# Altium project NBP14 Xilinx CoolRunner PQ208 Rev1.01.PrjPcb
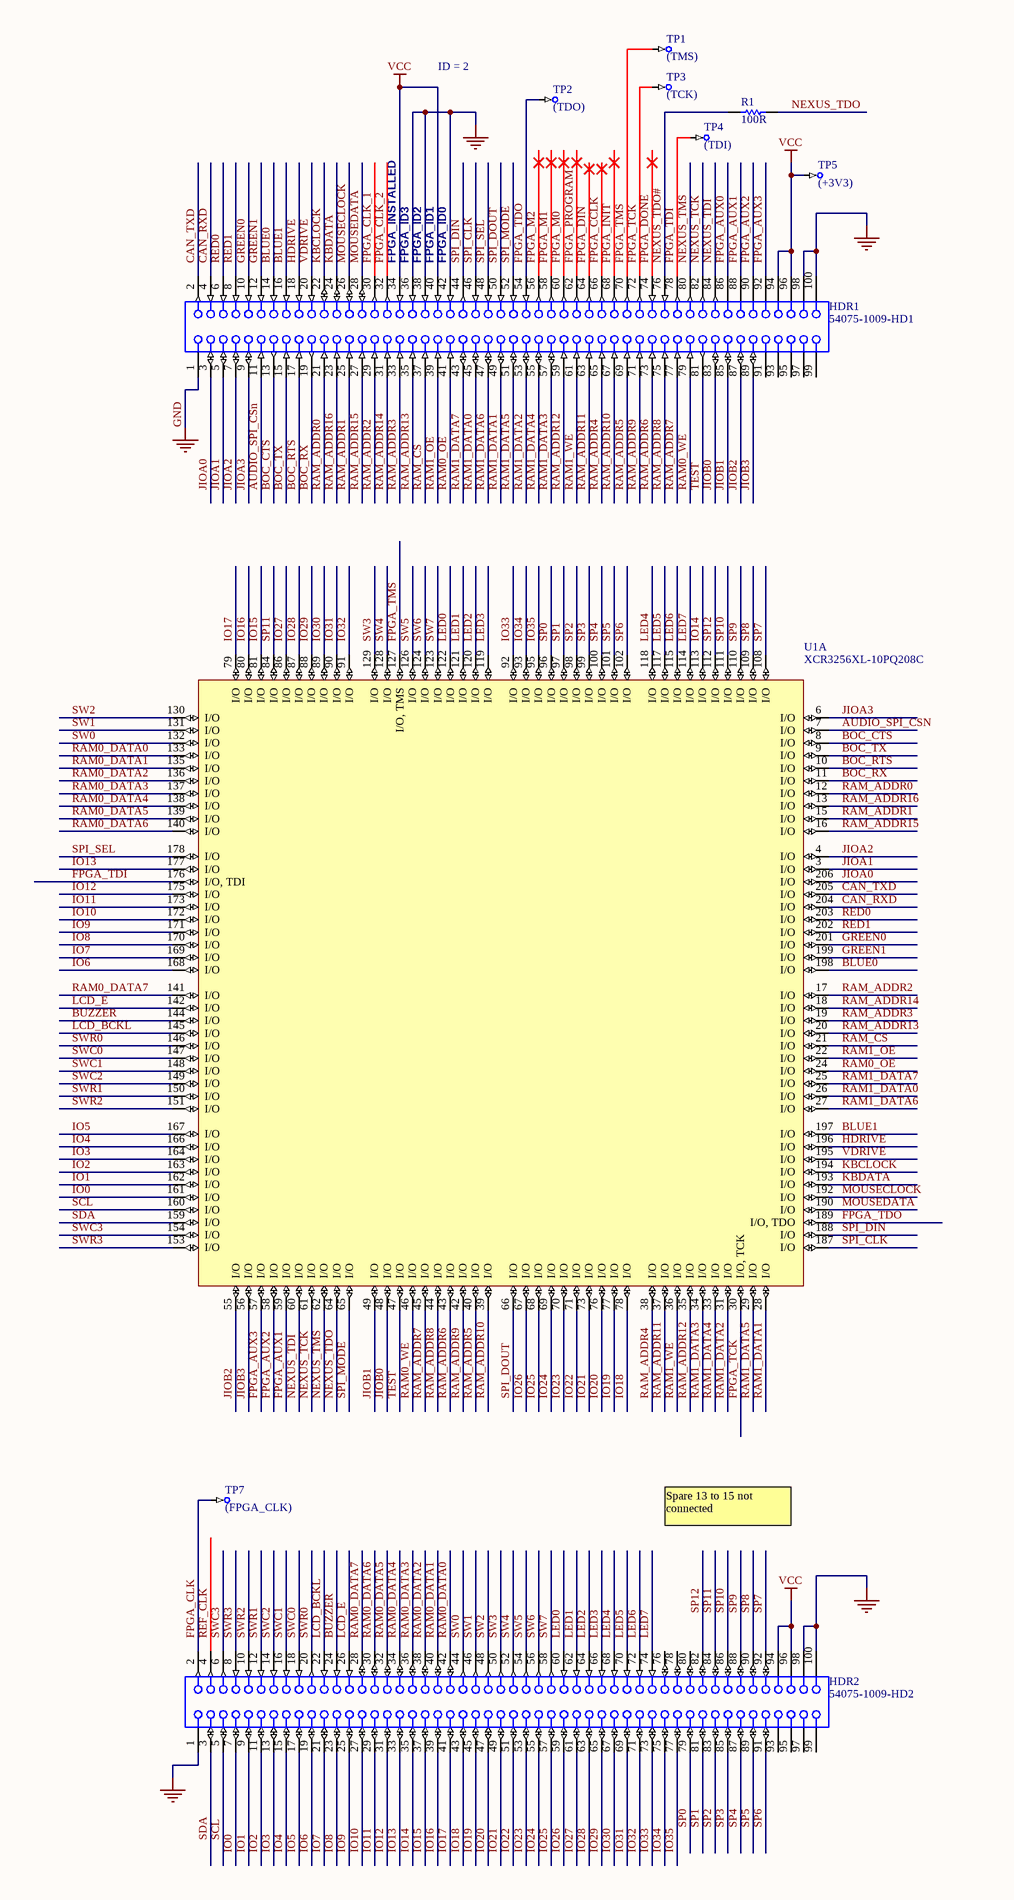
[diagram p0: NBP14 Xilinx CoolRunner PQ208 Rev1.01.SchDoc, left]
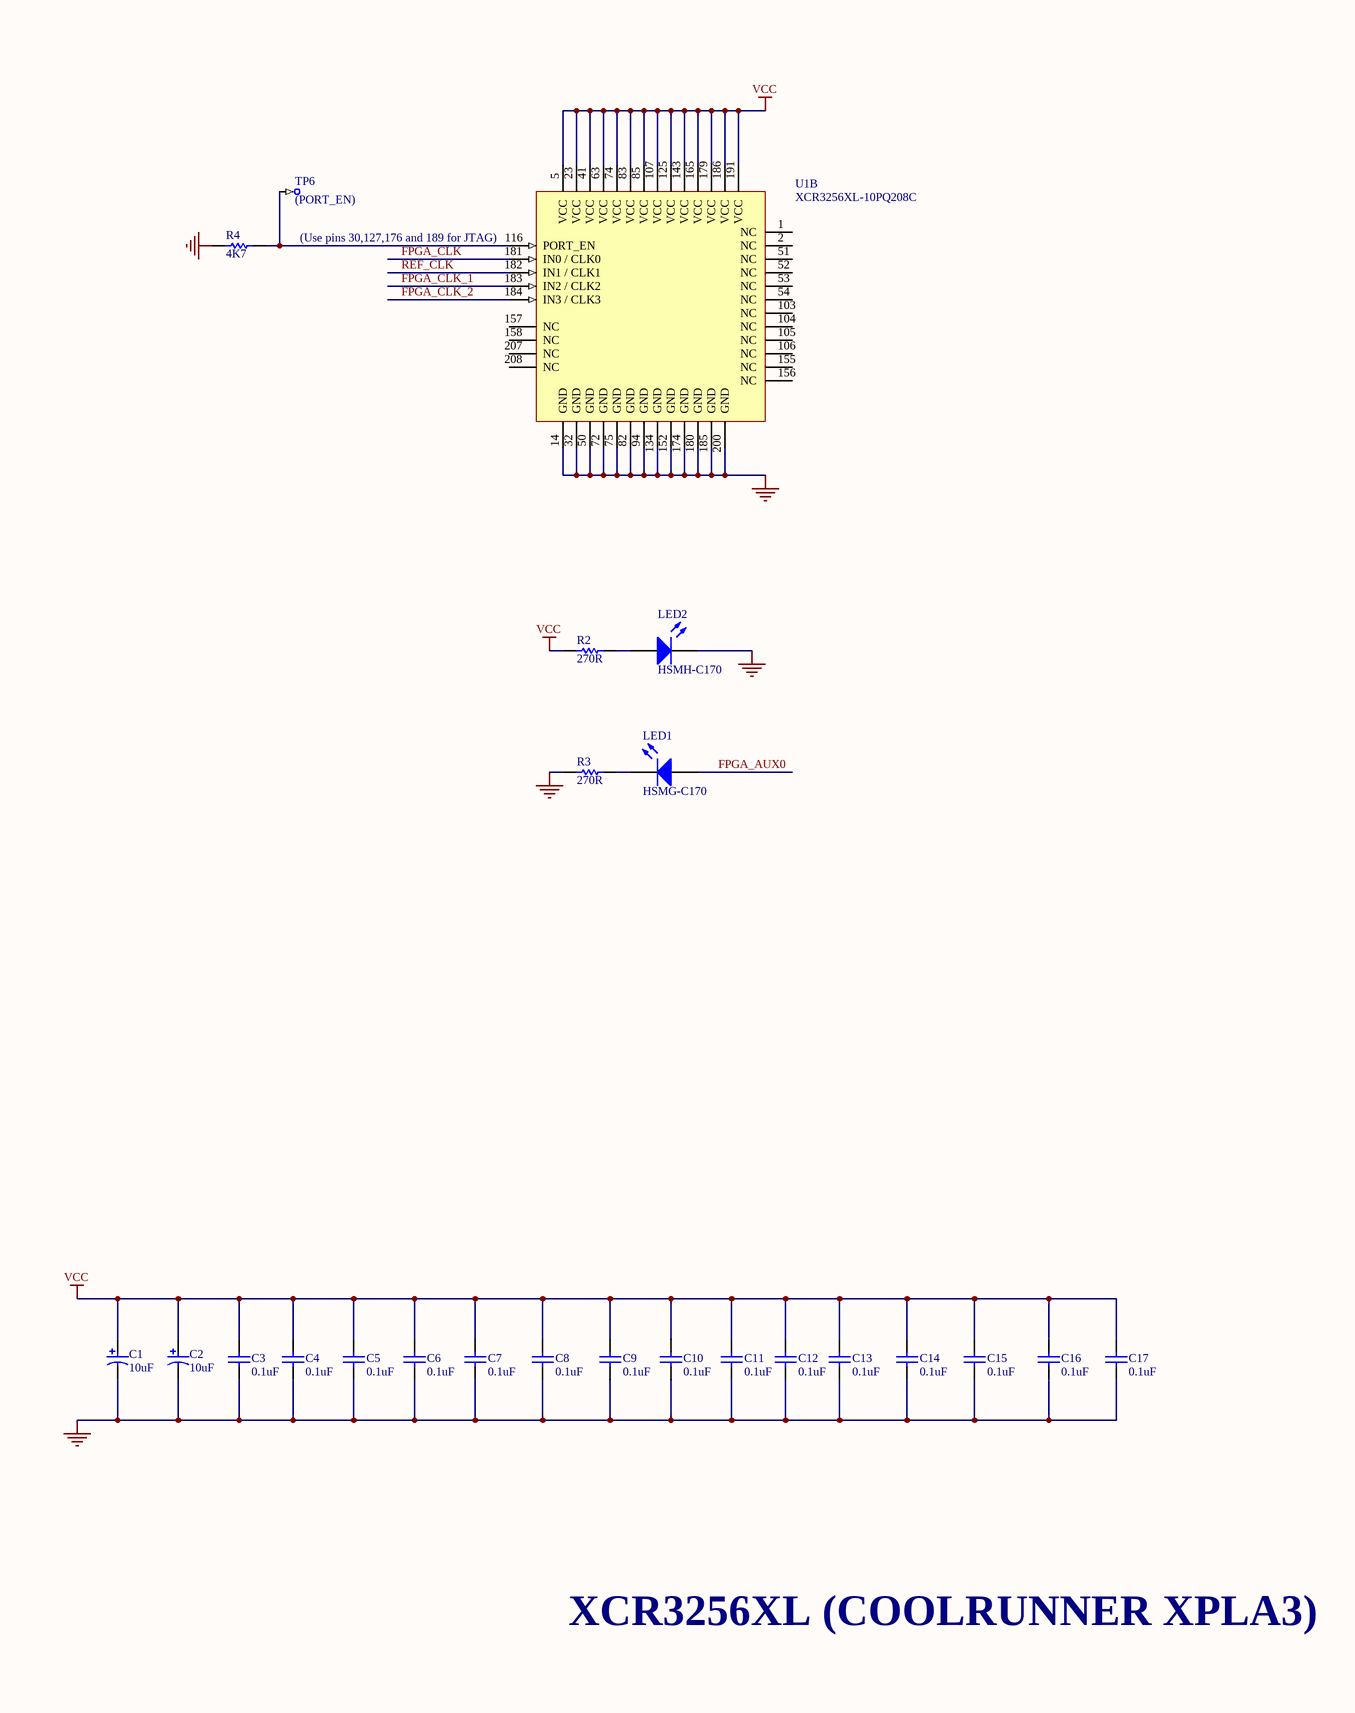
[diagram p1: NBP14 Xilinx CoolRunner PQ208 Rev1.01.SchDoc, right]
1 sheet, 33 parts. Net scope: global (net labels, ports and power ports of the same name join across sheets).
Board file: NBP14 Xilinx CoolRunner PQ208 Rev1.01.PcbDoc

## Sheet NBP14 Xilinx CoolRunner PQ208 Rev1.01.SchDoc: CoolRunner XPLA3 Daughter Board
size A2; Organization: Altium Limited; Address1: L3, 12a Rodborough Rd; Address2: Frenchs Forest; Address3: NSW; Address4: Australia 2086; DocumentNumber: 1; Revision: 1.01; SheetNumber: 1; SheetTotal: 1

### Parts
C1  10uF  [MCCT-B]
C2  10uF  [MCCT-B]
C3  0.1uF  [CC2012-0805]
C4  0.1uF  [CC2012-0805]
C5  0.1uF  [CC2012-0805]
C6  0.1uF  [CC2012-0805]
C7  0.1uF  [CC2012-0805]
C8  0.1uF  [CC2012-0805]
C9  0.1uF  [CC2012-0805]
C10  0.1uF  [CC2012-0805]
C11  0.1uF  [CC2012-0805]
C12  0.1uF  [CC2012-0805]
C13  0.1uF  [CC2012-0805]
C14  0.1uF  [CC2012-0805]
C15  0.1uF  [CC2012-0805]
C16  0.1uF  [CC2012-0805]
C17  0.1uF  [CC2012-0805]
HDR1  54075-1009-HD1  [54075]
HDR2  54075-1009-HD2  [54075]
LED1  HSMG-C170  [SMD _LED]
LED2  HSMH-C170  [SMD _LED]
R1  100R  [CC2012-0805]
R2  270R  [CC2012-0805]
R3  270R  [CC2012-0805]
R4  4K7  [CC2012-0805]
TP1  (TMS)  [TestPin]  (no BOM)
TP2  (TDO)  [TestPin]  (no BOM)
TP3  (TCK)  [TestPin]  (no BOM)
TP4  (TDI)  [TestPin]  (no BOM)
TP5  (+3V3)  [TestPin]  (no BOM)
TP6  (PORT_EN)  [TestPin]  (no BOM)
TP7  (FPGA_CLK)  [TestPin]  (no BOM)
U1  XCR3256XL-10PQ208C  [PQ208]  (parts A,B of 2)

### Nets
GND: C1.2 C2.2 C3.2 C4.2 C5.2 C6.2 C7.2 C8.2 C9.2 C10.2 C11.2 C12.2 C13.2 C14.2 C15.2 C16.2 C17.2 HDR1.1 HDR1.36 HDR1.38 HDR1.42 HDR1.98 HDR1.100 HDR2.1 HDR2.98 HDR2.100 LED2.2(K) R3.1 R4.1 U1.14(GND) U1.32(GND) U1.50(GND) U1.72(GND) U1.75(GND) U1.82(GND) U1.94(GND) U1.134(GND) U1.152(GND) U1.174(GND) U1.180(GND) U1.185(GND) U1.200(GND)
VCC: C1.1 C2.1 C3.1 C4.1 C5.1 C6.1 C7.1 C8.1 C9.1 C10.1 C11.1 C12.1 C13.1 C14.1 C15.1 C16.1 C17.1 HDR1.34 HDR1.40 HDR1.94 HDR1.96 HDR2.94 HDR2.96 R2.1 TP5.1 U1.5(VCC) U1.23(VCC) U1.41(VCC) U1.63(VCC) U1.74(VCC) U1.83(VCC) U1.85(VCC) U1.107(VCC) U1.125(VCC) U1.143(VCC) U1.165(VCC) U1.179(VCC) U1.186(VCC) U1.191(VCC)
AUDIO_SPI_CSn: HDR1.11 U1.7(I/O)
BLUE0: HDR1.14 U1.198(I/O)
BLUE1: HDR1.16 U1.197(I/O)
BOC_CTS: HDR1.13 U1.8(I/O)
BOC_RTS: HDR1.17 U1.10(I/O)
BOC_RX: HDR1.19 U1.11(I/O)
BOC_TX: HDR1.15 U1.9(I/O)
BUZZER: HDR2.24 U1.144(I/O)
CAN_RXD: HDR1.4 U1.204(I/O)
CAN_TXD: HDR1.2 U1.205(I/O)
FPGA_AUX0: HDR1.86 LED1.1(A)
FPGA_AUX1: HDR1.88 U1.59(I/O)
FPGA_AUX2: HDR1.90 U1.58(I/O)
FPGA_AUX3: HDR1.92 U1.57(I/O)
FPGA_CCLK: HDR1.66
FPGA_CLK: HDR2.2 TP7.1 U1.181(IN0_/_CLK0)
FPGA_CLK_1: HDR1.30 U1.183(IN2_/_CLK2)
FPGA_CLK_2: HDR1.32 U1.184(IN3_/_CLK3)
FPGA_DIN: HDR1.64
FPGA_DONE: HDR1.74
FPGA_INIT: HDR1.68
FPGA_M0: HDR1.60
FPGA_M1: HDR1.58
FPGA_M2: HDR1.56
FPGA_PROGRAM: HDR1.62
FPGA_TCK: HDR1.72 TP3.1 U1.30(I/O,_TCK)
FPGA_TDI: HDR1.78 TP4.1 U1.176(I/O,_TDI)
FPGA_TDO: HDR1.54 TP2.1 U1.189(I/O,_TDO)
FPGA_TMS: HDR1.70 TP1.1 U1.127(I/O,_TMS)
GREEN0: HDR1.10 U1.201(I/O)
GREEN1: HDR1.12 U1.199(I/O)
HDRIVE: HDR1.18 U1.196(I/O)
IO0: HDR2.7 U1.161(I/O)
IO1: HDR2.9 U1.162(I/O)
IO2: HDR2.11 U1.163(I/O)
IO3: HDR2.13 U1.164(I/O)
IO4: HDR2.15 U1.166(I/O)
IO5: HDR2.17 U1.167(I/O)
IO6: HDR2.19 U1.168(I/O)
IO7: HDR2.21 U1.169(I/O)
IO8: HDR2.23 U1.170(I/O)
IO9: HDR2.25 U1.171(I/O)
IO10: HDR2.27 U1.172(I/O)
IO11: HDR2.29 U1.173(I/O)
IO12: HDR2.31 U1.175(I/O)
IO13: HDR2.33 U1.177(I/O)
IO14: HDR2.35 U1.113(I/O)
IO15: HDR2.37 U1.81(I/O)
IO16: HDR2.39 U1.80(I/O)
IO17: HDR2.41 U1.79(I/O)
IO18: HDR2.43 U1.78(I/O)
IO19: HDR2.45 U1.77(I/O)
IO20: HDR2.47 U1.76(I/O)
IO21: HDR2.49 U1.73(I/O)
IO22: HDR2.51 U1.71(I/O)
IO23: HDR2.53 U1.70(I/O)
IO24: HDR2.55 U1.69(I/O)
IO25: HDR2.57 U1.68(I/O)
IO26: HDR2.59 U1.67(I/O)
IO27: HDR2.61 U1.86(I/O)
IO28: HDR2.63 U1.87(I/O)
IO29: HDR2.65 U1.88(I/O)
IO30: HDR2.67 U1.89(I/O)
IO31: HDR2.69 U1.90(I/O)
IO32: HDR2.71 U1.91(I/O)
IO33: HDR2.73 U1.92(I/O)
IO34: HDR2.75 U1.93(I/O)
IO35: HDR2.77 U1.95(I/O)
JIOA0: HDR1.3 U1.206(I/O)
JIOA1: HDR1.5 U1.3(I/O)
JIOA2: HDR1.7 U1.4(I/O)
JIOA3: HDR1.9 U1.6(I/O)
JIOB0: HDR1.83 U1.48(I/O)
JIOB1: HDR1.85 U1.49(I/O)
JIOB2: HDR1.87 U1.55(I/O)
JIOB3: HDR1.89 U1.56(I/O)
KBCLOCK: HDR1.22 U1.194(I/O)
KBDATA: HDR1.24 U1.193(I/O)
LCD_BCKL: HDR2.22 U1.145(I/O)
LCD_E: HDR2.26 U1.142(I/O)
LED0: HDR2.60 U1.122(I/O)
LED1: HDR2.62 U1.121(I/O)
LED2: HDR2.64 U1.120(I/O)
LED3: HDR2.66 U1.119(I/O)
LED4: HDR2.68 U1.118(I/O)
LED5: HDR2.70 U1.117(I/O)
LED6: HDR2.72 U1.115(I/O)
LED7: HDR2.74 U1.114(I/O)
MOUSECLOCK: HDR1.26 U1.192(I/O)
MOUSEDATA: HDR1.28 U1.190(I/O)
NEXUS_TCK: HDR1.82 U1.61(I/O)
NEXUS_TDI: HDR1.84 U1.60(I/O)
NEXUS_TDO: R1.2 U1.64(I/O)
NEXUS_TDO#: HDR1.76 R1.1
NEXUS_TMS: HDR1.80 U1.62(I/O)
RAM0_DATA0: HDR2.42 U1.133(I/O)
RAM0_DATA1: HDR2.40 U1.135(I/O)
RAM0_DATA2: HDR2.38 U1.136(I/O)
RAM0_DATA3: HDR2.36 U1.137(I/O)
RAM0_DATA4: HDR2.34 U1.138(I/O)
RAM0_DATA5: HDR2.32 U1.139(I/O)
RAM0_DATA6: HDR2.30 U1.140(I/O)
RAM0_DATA7: HDR2.28 U1.141(I/O)
RAM0_OE: HDR1.41 U1.24(I/O)
RAM0_WE: HDR1.79 U1.46(I/O)
RAM1_DATA0: HDR1.45 U1.26(I/O)
RAM1_DATA1: HDR1.49 U1.28(I/O)
RAM1_DATA2: HDR1.53 U1.31(I/O)
RAM1_DATA3: HDR1.57 U1.34(I/O)
RAM1_DATA4: HDR1.55 U1.33(I/O)
RAM1_DATA5: HDR1.51 U1.29(I/O)
RAM1_DATA6: HDR1.47 U1.27(I/O)
RAM1_DATA7: HDR1.43 U1.25(I/O)
RAM1_OE: HDR1.39 U1.22(I/O)
RAM1_WE: HDR1.61 U1.36(I/O)
RAM_ADDR0: HDR1.21 U1.12(I/O)
RAM_ADDR1: HDR1.25 U1.15(I/O)
RAM_ADDR2: HDR1.29 U1.17(I/O)
RAM_ADDR3: HDR1.33 U1.19(I/O)
RAM_ADDR4: HDR1.65 U1.38(I/O)
RAM_ADDR5: HDR1.69 U1.40(I/O)
RAM_ADDR6: HDR1.73 U1.43(I/O)
RAM_ADDR7: HDR1.77 U1.45(I/O)
RAM_ADDR8: HDR1.75 U1.44(I/O)
RAM_ADDR9: HDR1.71 U1.42(I/O)
RAM_ADDR10: HDR1.67 U1.39(I/O)
RAM_ADDR11: HDR1.63 U1.37(I/O)
RAM_ADDR12: HDR1.59 U1.35(I/O)
RAM_ADDR13: HDR1.35 U1.20(I/O)
RAM_ADDR14: HDR1.31 U1.18(I/O)
RAM_ADDR15: HDR1.27 U1.16(I/O)
RAM_ADDR16: HDR1.23 U1.13(I/O)
RAM_CS: HDR1.37 U1.21(I/O)
RED0: HDR1.6 U1.203(I/O)
RED1: HDR1.8 U1.202(I/O)
REF_CLK: HDR2.4 U1.182(IN1_/_CLK1)
SCL: HDR2.5 U1.160(I/O)
SDA: HDR2.3 U1.159(I/O)
SP0: HDR2.79 U1.96(I/O)
SP1: HDR2.81 U1.97(I/O)
SP2: HDR2.83 U1.98(I/O)
SP3: HDR2.85 U1.99(I/O)
SP4: HDR2.87 U1.100(I/O)
SP5: HDR2.89 U1.101(I/O)
SP6: HDR2.91 U1.102(I/O)
SP7: HDR2.92 U1.108(I/O)
SP8: HDR2.90 U1.109(I/O)
SP9: HDR2.88 U1.110(I/O)
SP10: HDR2.86 U1.111(I/O)
SP11: HDR2.84 U1.84(I/O)
SP12: HDR2.82 U1.112(I/O)
SPI_CLK: HDR1.46 U1.187(I/O)
SPI_DIN: HDR1.44 U1.188(I/O)
SPI_DOUT: HDR1.50 U1.66(I/O)
SPI_MODE: HDR1.52 U1.65(I/O)
SPI_SEL: HDR1.48 U1.178(I/O)
SW0: HDR2.44 U1.132(I/O)
SW1: HDR2.46 U1.131(I/O)
SW2: HDR2.48 U1.130(I/O)
SW3: HDR2.50 U1.129(I/O)
SW4: HDR2.52 U1.128(I/O)
SW5: HDR2.54 U1.126(I/O)
SW6: HDR2.56 U1.124(I/O)
SW7: HDR2.58 U1.123(I/O)
SWC0: HDR2.18 U1.147(I/O)
SWC1: HDR2.16 U1.148(I/O)
SWC2: HDR2.14 U1.149(I/O)
SWC3: HDR2.6 U1.154(I/O)
SWR0: HDR2.20 U1.146(I/O)
SWR1: HDR2.12 U1.150(I/O)
SWR2: HDR2.10 U1.151(I/O)
SWR3: HDR2.8 U1.153(I/O)
TEST: HDR1.81 U1.47(I/O)
VDRIVE: HDR1.20 U1.195(I/O)
NetLED1_2: LED1.2(K) R3.2
NetLED2_1: LED2.1(A) R2.2
NetR4_2: R4.2 TP6.1 U1.116(PORT_EN)

Not connected (* = marked no-connect by the designer): HDR1 91 93 95 97 99; HDR2 76 78 80 93 95 97 99; U1 1(NC) 2(NC) 51(NC) 52(NC) 53(NC) 54(NC) 103(NC) 104(NC) 105(NC) 106(NC) 155(NC) 156(NC) 157(NC) 158(NC) 207(NC) 208(NC)

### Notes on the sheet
- ID = 2
- (near HDR1) FPGA_INSTALLED
- (near HDR1) FPGA_ID3
- (near HDR1) FPGA_ID2
- (near HDR1) FPGA_ID1
- (near HDR1) FPGA_ID0
- (near U1) (Use pins 30,127,176 and 189 for JTAG)
- Spare 13 to 15 not connected
- XCR3256XL (COOLRUNNER XPLA3)

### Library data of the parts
C1 C2 = CAP_POLAR: Polar Capacitor
C3-C17 = CAP: Capacitor
HDR1 = 54075-1009-HD1: Board-to-Board, Docking Station, 0.80mm (.031") Pitch, Shielded Receptacle, Vertical, Ultra Low Profile, SMT; Manufacturer: Molex; Package Information: Latest Revision: Jun-2001; Mating Height: 8.5mm; Voltage: 100V; Current: 0.5A; Contact Resistance: 40mOhm max; PCB Layout: Complies with Manufacturer's Recommendation.
HDR2 = 54075-1009-HD2: Board-to-Board, Docking Station, 0.80mm (.031") Pitch, Shielded Receptacle, Vertical, Ultra Low Profile, SMT; Manufacturer: Molex; Package Information: Latest Revision: Jun-2001; Mating Height: 8.5mm; Voltage: 100V; Current: 0.5A; Contact Resistance: 40mOhm max; PCB Layout: Complies with Manufacturer's Recommendation.
LED1 LED2 = HSMX-C670: Typical RED GaAs SMD LED Agilent make; Manufacturer: Generic Components; Class I: Optoelectronic; Fitted: True
R1-R4 = RES: Resistor
TP1-TP7 = TestPin
U1 = XCR3256XL-10PQ208C: XCR3256XL CoolRunner XPLA3, 3.3 Volt, 256 Macrocell CPLD, 208-Pin PQFP, Commercial Grade; Package Information: Latest Revision: ver1.1, Oct-2002; Code - JEDEC: MS-029-FA-1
